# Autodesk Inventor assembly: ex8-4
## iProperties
Author: Administrator
Created: 2001-10
Part Number: ex8-4
Document SubType Name: Assembly
Designer: Administrator
Control State: 0
Master: False
Checked Out: False
PropertySet Name: Design Tracking Control
Shininess: 64.0
Angle Display Precision: 2
Document Length Units: 11272
Document Angle Units: 11286
Document Time Units: 11279
Document Mass Units: 11290
Document Length Units Precision: 3
Document Angle Units Precision: 2
Compacted: True
PropertySet Name: _Private Model Information
Density: 0.0
Volumn: 0.0
Area: 0.0
PropertySet Name: Model Information
